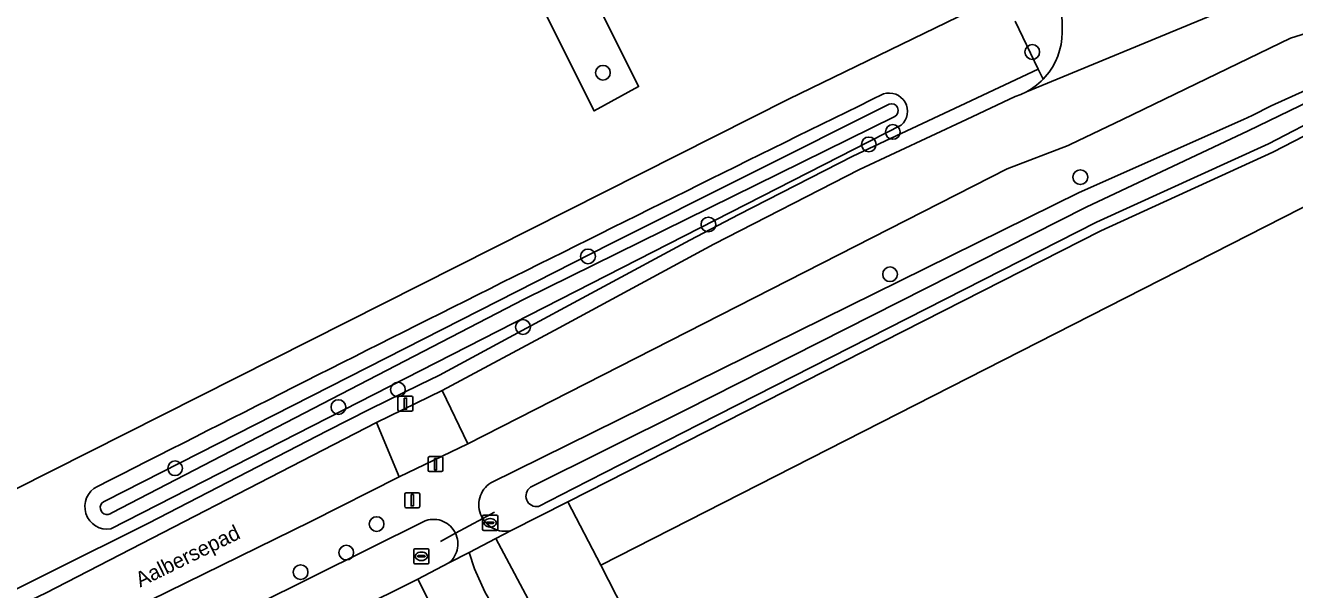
# Model space of a CAD drawing. Extents: x 162722 to 165104, y 384719 to 386284.
# Drawn here: x 163690.1 to 163774.4, y 385218.8 to 385256.2 of the extents above; entities that cross this region are included whole.
import ezdxf

# ---------------------------------------------------------------- set-up
doc = ezdxf.new("R2010")
doc.units = 0
for name, color, linetype in [('IMGEO_Afsluitpaal', 7, 'Continuous'), ('IMGEO_Boom', 7, 'Continuous'), ('IMGEO_Duiker', 7, 'Continuous'), ('IMGEO_Erf', 7, 'Continuous'), ('IMGEO_Gemengd_bos', 7, 'Continuous'), ('IMGEO_Grasland_agrarisch', 7, 'Continuous'), ('IMGEO_Groenvoorziening', 7, 'Continuous'), ('IMGEO_Hek', 7, 'Continuous'), ('IMGEO_Loofbos', 7, 'Continuous'), ('IMGEO_Oever', 7, 'Continuous'), ('IMGEO_Openbare_ruimte_label', 7, 'Continuous'), ('IMGEO_Rijbaan_lokaal_halfverhard', 7, 'Continuous'), ('IMGEO_Rijbaan_lokaal_open', 7, 'Continuous'), ('IMGEO_Rioolput', 7, 'Continuous'), ('IMGEO_Voetpad_onverhard', 7, 'Continuous'), ('IMGEO_Waterloop', 7, 'Continuous')]:
    doc.layers.add(name, color=color, linetype=linetype)

msp = doc.modelspace()

# ---------------------------------------------------------------- linework, layer by layer
at = {"layer": 'IMGEO_Afsluitpaal'}
for p, q in [((163714.925, 385231.608), (163715.715, 385231.608)), ((163715.715, 385231.608), (163714.925, 385231.608)), ((163714.825, 385230.708), (163714.825, 385231.508)), ((163714.825, 385231.508), (163714.825, 385230.708)), ((163715.815, 385231.508), (163715.815, 385230.708)), ((163715.815, 385230.708), (163715.815, 385231.508)), ((163715.715, 385230.608), (163714.925, 385230.608)), ((163714.925, 385230.608), (163715.715, 385230.608)), ((163716.822, 385226.692), (163716.822, 385227.492)), ((163716.822, 385227.492), (163716.822, 385226.692)), ((163716.922, 385227.592), (163717.712, 385227.592)), ((163717.712, 385227.592), (163716.922, 385227.592)), ((163717.812, 385227.492), (163717.812, 385226.692)), ((163717.812, 385226.692), (163717.812, 385227.492)), ((163717.712, 385226.592), (163716.922, 385226.592)), ((163716.922, 385226.592), (163717.712, 385226.592)), ((163715.279, 385224.29), (163715.279, 385225.09)), ((163715.279, 385225.09), (163715.279, 385224.29)), ((163715.379, 385225.19), (163716.169, 385225.19)), ((163716.169, 385225.19), (163715.379, 385225.19)), ((163716.269, 385225.09), (163716.269, 385224.29)), ((163716.269, 385224.29), (163716.269, 385225.09)), ((163716.169, 385224.19), (163715.379, 385224.19)), ((163715.379, 385224.19), (163716.169, 385224.19))]:
    msp.add_line(p, q, dxfattribs=at)
for points in [[(163715.245, 385231.483), (163715.395, 385231.483), (163715.395, 385230.733), (163715.245, 385230.733), (163715.245, 385231.483)], [(163717.242, 385227.467), (163717.392, 385227.467), (163717.392, 385226.717), (163717.242, 385226.717), (163717.242, 385227.467)], [(163715.699, 385225.065), (163715.849, 385225.065), (163715.849, 385224.315), (163715.699, 385224.315), (163715.699, 385225.065)]]:
    msp.add_lwpolyline(points, dxfattribs=at)
for centre, start, end in [((163714.925, 385231.508), 90, 180), ((163714.925, 385231.508), 90, 180), ((163715.715, 385231.508), 0, 90), ((163715.715, 385231.508), 360, 90), ((163714.925, 385230.708), 180, 270), ((163714.925, 385230.708), 180, 270), ((163715.715, 385230.708), 270, 0), ((163715.715, 385230.708), 270, 0), ((163716.922, 385227.492), 90, 180), ((163716.922, 385227.492), 90, 180), ((163717.712, 385227.492), 0, 90), ((163717.712, 385227.492), 360, 90), ((163716.922, 385226.692), 180, 270), ((163716.922, 385226.692), 180, 270), ((163717.712, 385226.692), 270, 0), ((163717.712, 385226.692), 270, 0), ((163715.379, 385225.09), 90, 180), ((163715.379, 385225.09), 90, 180), ((163716.169, 385225.09), 0, 90), ((163716.169, 385225.09), 360, 90), ((163715.379, 385224.29), 180, 270), ((163715.379, 385224.29), 180, 270), ((163716.169, 385224.29), 270, 0), ((163716.169, 385224.29), 270, 0)]:
    msp.add_arc(centre, 0.1, start, end, dxfattribs=at)
at = {"layer": 'IMGEO_Boom'}
for centre in [(163756.99, 385254.474), (163728.452, 385253.098), (163747.72, 385249.161), (163746.126, 385248.334), (163760.187, 385246.159), (163735.458, 385243.015), (163727.456, 385240.893), (163747.537, 385239.705), (163723.134, 385236.202), (163714.821, 385232.047), (163710.861, 385230.882), (163700.008, 385226.815), (163713.404, 385223.11), (163711.387, 385221.214), (163708.349, 385219.914)]:
    msp.add_circle(centre, 0.489, dxfattribs=at)
at = {"layer": 'IMGEO_Duiker'}
msp.add_lwpolyline([(163721.239, 385223.894), (163720.457, 385223.472), (163718.65, 385222.495), (163717.642, 385221.951)], dxfattribs=at)
at = {"layer": 'IMGEO_Erf'}
msp.add_lwpolyline([(163910.133, 385241.022), (163886.57, 385243.212), (163810.294, 385250), (163789.963, 385251.774), (163786.457, 385250), (163728.314, 385220.373), (163748.353, 385181.193), (163771.607, 385192.983), (163778.051, 385196.25), (163781.022, 385197.731)], dxfattribs=at)
at = {"layer": 'IMGEO_Gemengd_bos'}
msp.add_lwpolyline([(163728.314, 385220.373), (163786.457, 385250), (163789.963, 385251.774), (163810.294, 385250), (163886.57, 385243.212), (163910.133, 385241.022), (163910.573, 385246.191), (163871.205, 385250), (163855.681, 385251.502), (163834.151, 385252.659), (163805.574, 385255.278), (163801.35, 385255.558), (163797.117, 385255.46), (163792.91, 385254.985), (163788.763, 385254.135), (163788.312, 385254.019), (163782.99, 385252.393), (163777.835, 385250.299), (163777.194, 385250), (163772.987, 385247.809), (163761.54, 385242.598), (163726.113, 385224.584)], close=True, dxfattribs=at)
at = {"layer": 'IMGEO_Grasland_agrarisch'}
for points in [[(163649.843, 385273.666), (163612.723, 385253.417), (163611.945, 385253.297), (163611.089, 385253.789), (163582.086, 385306.805), (163581.429, 385306.477), (163540.181, 385285.869), (163543.916, 385277.299), (163557.512, 385250), (163593.927, 385177.311), (163740.778, 385251.339), (163752.789, 385257.167), (163698.901, 385364.116), (163630.385, 385330.124), (163622.467, 385326.196)], [(163685.932, 385342.044), (163730.824, 385252.178), (163727.861, 385250.558), (163682.789, 385340.505)]]:
    msp.add_lwpolyline(points, close=True, dxfattribs=at)
at = {"layer": 'IMGEO_Groenvoorziening'}
for points in [[(163685.932, 385342.044), (163682.789, 385340.505), (163727.861, 385250.558), (163730.824, 385252.178)], [(163726.113, 385224.584), (163722.356, 385222.674), (163721.329, 385222.143), (163724.011, 385217.113), (163729.086, 385209.009), (163731.604, 385205.593), (163735.842, 385197.581), (163744.855, 385179.419), (163748.353, 385181.193), (163728.314, 385220.373)], [(163719.548, 385221.223), (163719.919, 385220.14), (163720.588, 385218.607), (163723.491, 385213.575), (163729.649, 385204.624), (163733.239, 385197.673), (163742.936, 385178.446), (163744.855, 385179.419), (163735.842, 385197.581), (163731.604, 385205.593), (163729.086, 385209.009), (163724.011, 385217.113), (163721.329, 385222.143)], [(163718.262, 385215.236), (163738.041, 385175.965), (163742.936, 385178.446), (163733.239, 385197.673), (163729.649, 385204.624), (163723.491, 385213.575), (163720.588, 385218.607), (163719.919, 385220.14), (163719.548, 385221.223), (163718.214, 385220.533), (163716.137, 385219.455)], [(163697.355, 385204.78), (163718.262, 385215.236), (163716.137, 385219.455), (163582.606, 385153.065), (163572.284, 385147.71), (163567.284, 385144.313), (163558.104, 385140.325), (163559.746, 385137.091), (163591.679, 385153.256), (163626.169, 385170.846), (163627.133, 385169.047)]]:
    msp.add_lwpolyline(points, close=True, dxfattribs=at)
for points in [[(163777.7, 385256.496), (163774.167, 385255.4), (163762.995, 385250), (163759.521, 385248.321), (163759.373, 385248.264), (163755.332, 385246.722), (163719.457, 385228.444), (163714.908, 385226.251), (163709.029, 385223.291), (163695.982, 385216.891), (163624.905, 385180.679)], [(163580.895, 385155.915), (163716.621, 385223.327), (163716.688, 385223.35), (163716.829, 385223.387), (163716.973, 385223.412), (163717.118, 385223.424), (163717.264, 385223.423), (163717.409, 385223.408), (163717.552, 385223.381), (163717.693, 385223.341), (163717.829, 385223.289), (163717.96, 385223.225), (163718.084, 385223.149), (163718.202, 385223.063), (163718.311, 385222.966), (163718.411, 385222.86), (163718.502, 385222.746), (163718.581, 385222.624), (163718.65, 385222.495), (163718.698, 385222.385), (163718.744, 385222.246), (163718.779, 385222.104), (163718.8, 385221.96), (163718.808, 385221.814), (163718.804, 385221.668), (163718.786, 385221.523), (163718.756, 385221.381), (163718.712, 385221.241), (163718.657, 385221.106), (163718.59, 385220.977), (163718.511, 385220.854), (163718.422, 385220.738), (163718.323, 385220.631), (163718.214, 385220.533), (163719.548, 385221.223), (163721.329, 385222.143), (163722.356, 385222.674), (163722.205, 385222.646), (163722.048, 385222.631), (163721.891, 385222.63), (163721.734, 385222.643), (163721.579, 385222.67), (163721.427, 385222.711), (163721.279, 385222.765), (163721.137, 385222.833), (163721.001, 385222.912), (163720.873, 385223.004), (163720.754, 385223.106), (163720.644, 385223.219), (163720.545, 385223.341), (163720.457, 385223.472), (163720.447, 385223.489), (163720.373, 385223.628), (163720.311, 385223.772), (163720.263, 385223.922), (163720.228, 385224.076), (163720.207, 385224.232), (163720.2, 385224.389), (163720.207, 385224.547), (163720.228, 385224.703), (163720.263, 385224.856), (163720.312, 385225.006), (163720.374, 385225.151), (163720.448, 385225.289), (163720.535, 385225.421), (163720.633, 385225.544), (163720.741, 385225.658), (163720.86, 385225.762), (163720.987, 385225.855), (163760.118, 385245.135), (163771.039, 385250), (163771.62, 385250.259), (163772.877, 385250.908), (163779.988, 385254.117)], [(163691.382, 385218.519), (163713.395, 385229.852), (163717.752, 385231.973), (163725.535, 385236.149), (163735.822, 385241.702), (163745.512, 385246.664), (163752.626, 385250), (163755.859, 385251.516), (163756.237, 385251.657), (163756.6, 385251.831), (163756.947, 385252.037), (163757.274, 385252.273), (163757.578, 385252.537), (163757.706, 385252.671), (163757.387, 385253.337), (163752.201, 385250.905), (163745.056, 385247.554), (163737.476, 385243.672), (163734.234, 385241.981), (163722.212, 385235.501), (163717.573, 385233.012), (163716.246, 385232.352), (163712.957, 385230.751), (163710.127, 385229.294), (163698.248, 385223.179), (163685.195, 385216.689)]]:
    msp.add_lwpolyline(points, dxfattribs=at)
at = {"layer": 'IMGEO_Hek'}
msp.add_lwpolyline([(163727.861, 385250.558), (163682.789, 385340.505), (163685.932, 385342.044), (163730.824, 385252.178), (163727.861, 385250.558)], dxfattribs=at)
at = {"layer": 'IMGEO_Loofbos'}
msp.add_lwpolyline([(163593.927, 385177.311), (163557.512, 385250), (163543.916, 385277.299), (163540.181, 385285.869), (163581.429, 385306.477), (163582.086, 385306.805), (163583.484, 385307.504), (163622.467, 385326.196), (163630.385, 385330.124), (163698.901, 385364.116), (163752.789, 385257.167), (163740.778, 385251.339)], close=True, dxfattribs=at)
for points in [[(163755.86, 385256.529), (163757.387, 385253.337), (163757.706, 385252.671), (163757.857, 385252.828), (163758.11, 385253.142), (163758.333, 385253.477), (163758.526, 385253.832), (163758.686, 385254.201), (163758.812, 385254.584), (163758.904, 385254.977), (163758.961, 385255.376), (163758.981, 385255.778), (163758.978, 385256.512), (163758.91, 385257.243), (163758.777, 385257.965), (163758.58, 385258.672), (163758.32, 385259.359), (163758.001, 385260.019), (163757.623, 385260.649), (163757.295, 385261.109), (163753.419, 385268.007), (163751.105, 385271.767), (163746.223, 385281.578), (163729.05, 385314.503)], [(163685.195, 385216.689), (163698.248, 385223.179), (163710.127, 385229.294), (163712.957, 385230.751), (163716.246, 385232.352), (163717.573, 385233.012), (163722.212, 385235.501), (163734.234, 385241.981), (163737.476, 385243.672), (163745.056, 385247.554), (163752.201, 385250.905), (163757.387, 385253.337), (163755.86, 385256.529)], [(163748.275, 385249.617), (163695.744, 385222.786)]]:
    msp.add_lwpolyline(points, dxfattribs=at)
for centre, radius, start, end in [((165519.651, 381635.629), 4027.138, 116.113636, 116.944509), ((163747.477, 385250.534), 1.216, 311.01406, 108.33259), ((163695.502, 385224.261), 1.495, 116.0865, 279.301)]:
    msp.add_arc(centre, radius, start, end, dxfattribs=at)
at = {"layer": 'IMGEO_Oever'}
for points in [[(163723.635, 385225.559), (163733.915, 385230.675), (163760.585, 385244.169), (163771.339, 385249.229), (163780.225, 385253.523), (163787.537, 385256.063), (163789.688, 385256.57), (163792.368, 385256.924), (163797.592, 385257.005), (163801.506, 385257.021), (163805.639, 385256.698), (163834.243, 385254.136), (163855.663, 385252.919), (163892.589, 385249.365), (163910.526, 385247.41)], [(163910.571, 385246.849), (163910.38, 385246.851), (163871.267, 385250.636), (163855.729, 385252.139), (163834.197, 385253.296), (163805.624, 385255.915), (163801.364, 385256.197), (163797.074, 385256.098), (163792.447, 385256.152), (163787.987, 385255.362), (163780.569, 385252.718), (163776.621, 385250.4), (163772.707, 385248.383), (163761.263, 385243.174), (163734.828, 385229.732), (163726.485, 385225.462), (163724.159, 385224.28)], [(163779.988, 385254.117), (163772.877, 385250.908), (163771.62, 385250.259), (163771.039, 385250), (163760.118, 385245.135), (163720.987, 385225.855), (163720.86, 385225.762), (163720.741, 385225.658), (163720.633, 385225.544), (163720.535, 385225.421), (163720.448, 385225.289), (163720.374, 385225.151), (163720.312, 385225.006), (163720.263, 385224.856), (163720.228, 385224.703), (163720.207, 385224.547), (163720.2, 385224.389), (163720.207, 385224.232), (163720.228, 385224.076), (163720.263, 385223.922), (163720.311, 385223.772), (163720.373, 385223.628), (163720.447, 385223.489), (163720.457, 385223.472), (163720.545, 385223.341), (163720.644, 385223.219), (163720.754, 385223.106), (163720.873, 385223.004), (163721.001, 385222.912), (163721.137, 385222.833), (163721.279, 385222.765), (163721.427, 385222.711), (163721.579, 385222.67), (163721.734, 385222.643), (163721.891, 385222.63), (163722.048, 385222.631), (163722.205, 385222.646), (163722.356, 385222.674), (163726.113, 385224.584), (163761.54, 385242.598), (163772.987, 385247.809), (163777.194, 385250)], [(163695.379, 385224.647), (163728.947, 385241.723), (163747.477, 385251.016)], [(163747.863, 385250.197), (163723.217, 385238.049), (163695.801, 385223.856)], [(163695.744, 385222.786), (163748.275, 385249.617)]]:
    msp.add_lwpolyline(points, dxfattribs=at)
for centre, radius, start, end in [((165519.651, 381635.629), 4027.138, 116.113636, 116.944509), ((163747.477, 385250.534), 1.216, 311.01406, 108.33259), ((163747.622, 385250.584), 0.456, 301.86902, 108.60059), ((163695.502, 385224.261), 1.495, 116.0865, 279.301), ((163724.038, 385224.977), 0.708, 124.75472, 279.80263), ((163695.491, 385224.199), 0.462, 104.04662, 312.11339)]:
    msp.add_arc(centre, radius, start, end, dxfattribs=at)
at = {"layer": 'IMGEO_Rijbaan_lokaal_halfverhard'}
msp.add_lwpolyline([(163768.949, 385256.914), (163756.6, 385251.831), (163756.237, 385251.657), (163755.859, 385251.516), (163752.626, 385250), (163745.512, 385246.664), (163735.822, 385241.702), (163725.535, 385236.149), (163717.752, 385231.973), (163719.457, 385228.444), (163755.332, 385246.722), (163759.373, 385248.264), (163759.521, 385248.321), (163762.995, 385250), (163774.167, 385255.4), (163777.7, 385256.496)], dxfattribs=at)
msp.add_lwpolyline([(163592.073, 385168.566), (163582.764, 385163.624), (163584.248, 385160.553), (163586.161, 385161.547), (163600.475, 385168.619), (163605.526, 385170.964), (163618.659, 385177.795), (163624.905, 385180.679), (163695.982, 385216.891), (163709.029, 385223.291), (163714.908, 385226.251), (163713.395, 385229.852), (163691.382, 385218.519), (163675.753, 385211.099), (163668.525, 385207.138), (163641.983, 385193.656), (163632.849, 385188.828), (163621.537, 385183.16), (163617.772, 385181.513), (163611.279, 385177.903), (163603.673, 385174.051), (163594.305, 385169.758)], close=True, dxfattribs=at)
at = {"layer": 'IMGEO_Rijbaan_lokaal_open'}
msp.add_lwpolyline([(163714.908, 385226.251), (163719.457, 385228.444), (163717.752, 385231.973), (163713.395, 385229.852)], close=True, dxfattribs=at)
at = {"layer": 'IMGEO_Rioolput'}
for p, q in [((163720.452, 385222.767), (163720.452, 385223.619)), ((163720.527, 385223.693), (163721.379, 385223.693)), ((163720.711, 385223.187), (163720.711, 385223.199)), ((163721.149, 385223.15), (163720.751, 385223.15)), ((163720.754, 385223.236), (163721.152, 385223.236)), ((163720.94, 385223.473), (163720.965, 385223.473)), ((163721.195, 385223.199), (163721.195, 385223.187)), ((163721.453, 385223.619), (163721.453, 385222.767)), ((163721.379, 385222.693), (163720.527, 385222.693)), ((163720.963, 385222.913), (163720.938, 385222.913)), ((163715.955, 385221.469), (163716.807, 385221.469)), ((163715.88, 385220.543), (163715.88, 385221.395)), ((163716.139, 385220.963), (163716.139, 385220.975)), ((163716.577, 385220.926), (163716.179, 385220.926)), ((163716.182, 385221.012), (163716.58, 385221.012)), ((163716.391, 385220.689), (163716.366, 385220.689)), ((163716.368, 385221.249), (163716.393, 385221.249)), ((163716.623, 385220.975), (163716.623, 385220.963)), ((163716.881, 385221.395), (163716.881, 385220.543)), ((163716.807, 385220.469), (163715.955, 385220.469))]:
    msp.add_line(p, q, dxfattribs=at)
for points in [[(163720.452, 385222.767), (163720.452, 385223.619)], [(163720.527, 385223.693), (163721.379, 385223.693)], [(163721.453, 385223.619), (163721.453, 385222.767)], [(163721.379, 385222.693), (163720.527, 385222.693)], [(163715.955, 385221.469), (163716.807, 385221.469)], [(163715.88, 385220.543), (163715.88, 385221.395)], [(163716.881, 385221.395), (163716.881, 385220.543)], [(163716.807, 385220.469), (163715.955, 385220.469)]]:
    msp.add_lwpolyline(points, dxfattribs=at)
for centre, radius, start, end in [((163720.529, 385223.617), 0.0765, 91.55205, 178.44795), ((163720.529, 385223.617), 0.0765, 91.55205, 178.44795), ((163720.751, 385223.196), 0.0403, 85.87752, 175.75265), ((163720.748, 385223.186), 0.0366, 178.93798, 274.71019), ((163721.152, 385223.193), 0.043, 264.86636, 352.45326), ((163721.156, 385223.198), 0.0386, 1.73085, 96.63898), ((163721.377, 385223.617), 0.0765, 1.55205, 88.44795), ((163721.377, 385223.617), 0.0765, 1.55205, 88.44795), ((163720.529, 385222.769), 0.0765, 181.55205, 268.44795), ((163720.529, 385222.769), 0.0765, 181.55205, 268.44795), ((163721.377, 385222.769), 0.0765, 271.55205, 358.44795), ((163721.377, 385222.769), 0.0765, 271.55205, 358.44795), ((163715.957, 385221.393), 0.0765, 91.55205, 178.44795), ((163715.957, 385221.393), 0.0765, 91.55205, 178.44795), ((163716.805, 385221.393), 0.0765, 1.55205, 88.44795), ((163716.805, 385221.393), 0.0765, 1.55205, 88.44795), ((163716.179, 385220.972), 0.0403, 85.87752, 175.75265), ((163716.176, 385220.962), 0.0366, 178.93798, 274.71019), ((163716.58, 385220.969), 0.043, 264.86636, 352.45326), ((163716.584, 385220.974), 0.0386, 1.73085, 96.63898), ((163715.957, 385220.545), 0.0765, 181.55205, 268.44795), ((163715.957, 385220.545), 0.0765, 181.55205, 268.44795), ((163716.805, 385220.545), 0.0765, 271.55205, 358.44795), ((163716.805, 385220.545), 0.0765, 271.55205, 358.44795)]:
    msp.add_arc(centre, radius, start, end, dxfattribs=at)
for centre, major_axis, ratio, start_param, end_param in [((163720.939, 385223.193), (-0.387, 0.002), 0.722429, 4.712389, 7.853982), ((163720.964, 385223.193), (-0.39, 0.002), 0.717154, 1.570796, 4.712389), ((163716.367, 385220.969), (-0.387, 0.002), 0.722429, 4.712389, 7.853982), ((163716.392, 385220.969), (-0.39, 0.002), 0.717154, 1.570796, 4.712389)]:
    msp.add_ellipse(centre, major_axis=major_axis, ratio=ratio, start_param=start_param, end_param=end_param, dxfattribs=at)
at = {"layer": 'IMGEO_Voetpad_onverhard'}
msp.add_lwpolyline([(163758.978, 385256.512), (163758.981, 385255.778), (163758.961, 385255.376), (163758.904, 385254.977), (163758.812, 385254.584), (163758.686, 385254.201), (163758.526, 385253.832), (163758.333, 385253.477), (163758.11, 385253.142), (163757.857, 385252.828), (163757.706, 385252.671), (163757.578, 385252.537), (163757.274, 385252.273), (163756.947, 385252.037), (163756.6, 385251.831), (163768.949, 385256.914)], dxfattribs=at)
at = {"layer": 'IMGEO_Waterloop'}
for points in [[(163910.526, 385247.41), (163892.589, 385249.365), (163855.663, 385252.919), (163834.243, 385254.136), (163805.639, 385256.698), (163801.506, 385257.021), (163797.592, 385257.005), (163792.368, 385256.924), (163789.688, 385256.57), (163787.537, 385256.063), (163780.225, 385253.523), (163771.339, 385249.229), (163760.585, 385244.169), (163733.915, 385230.675), (163723.635, 385225.559)], [(163724.159, 385224.28), (163726.485, 385225.462), (163734.828, 385229.732), (163761.263, 385243.174), (163772.707, 385248.383), (163776.621, 385250.4), (163780.569, 385252.718), (163787.987, 385255.362), (163792.447, 385256.152), (163797.074, 385256.098), (163801.364, 385256.197), (163805.624, 385255.915), (163834.197, 385253.296), (163855.729, 385252.139), (163871.267, 385250.636), (163910.38, 385246.851)], [(163747.477, 385251.016), (163728.947, 385241.723), (163695.379, 385224.647)], [(163695.801, 385223.856), (163723.217, 385238.049), (163747.863, 385250.197)], [(163582.606, 385153.065), (163716.137, 385219.455), (163718.214, 385220.533), (163718.323, 385220.631), (163718.422, 385220.738), (163718.511, 385220.854), (163718.59, 385220.977), (163718.657, 385221.106), (163718.712, 385221.241), (163718.756, 385221.381), (163718.786, 385221.523), (163718.804, 385221.668), (163718.808, 385221.814), (163718.8, 385221.96), (163718.779, 385222.104), (163718.744, 385222.246), (163718.698, 385222.385), (163718.65, 385222.495), (163718.581, 385222.624), (163718.502, 385222.746), (163718.411, 385222.86), (163718.311, 385222.966), (163718.202, 385223.063), (163718.084, 385223.149), (163717.96, 385223.225), (163717.829, 385223.289), (163717.693, 385223.341), (163717.552, 385223.381), (163717.409, 385223.408), (163717.264, 385223.423), (163717.118, 385223.424), (163716.973, 385223.412), (163716.829, 385223.387), (163716.688, 385223.35), (163716.621, 385223.327), (163580.895, 385155.915)]]:
    msp.add_lwpolyline(points, dxfattribs=at)
for centre, radius, start, end in [((163747.622, 385250.584), 0.456, 301.86902, 108.60059), ((163724.038, 385224.977), 0.708, 124.75472, 279.80263), ((163695.491, 385224.199), 0.462, 104.04662, 312.11339)]:
    msp.add_arc(centre, radius, start, end, dxfattribs=at)

# ---------------------------------------------------------------- texts
at = {"layer": 'IMGEO_Openbare_ruimte_label'}
msp.add_text('Aalbersepad', height=1, rotation=26.10382, dxfattribs=at).set_placement((163697.683, 385218.892))

doc.saveas('drawing.dxf')
